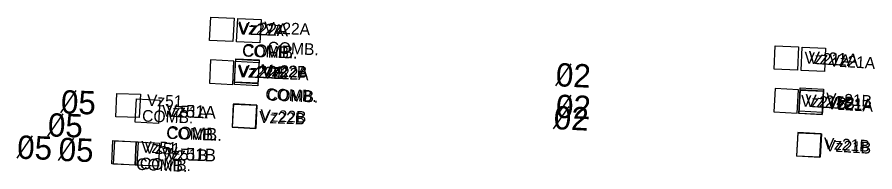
# Model space of a CAD drawing. Extents: x 647787 to 668496, y 640478 to 654412.
# Drawn here: x 660018.7 to 660238.8, y 647421.7 to 647461.5 of the extents above; entities that cross this region are included whole.
import ezdxf

# ---------------------------------------------------------------- set-up
doc = ezdxf.new("R2010")
doc.units = 0
for name, color, linetype in [('Default', 7, 'Continuous'), ('TEMP_DETECTION ZONE_Stage 2', 7, 'Continuous'), ('TEMP_DETECTION ZONE_STAGE 3', 7, 'Continuous'), ('TEMP_DETECTION_ZONE_STAGE 5', 7, 'Continuous'), ('TEMP_SIGNAL_POLES_STAGE 1B', 7, 'Continuous')]:
    doc.layers.add(name, color=color, linetype=linetype)

msp = doc.modelspace()

# ---------------------------------------------------------------- linework, layer by layer
at = {"layer": 'Default'}
for p, q in [((660156.89, 647443.78), (660160.86, 647449.48)), ((660156.89, 647443.78), (660160.86, 647449.48)), ((660156.89, 647443.78), (660160.86, 647449.48)), ((660029.94, 647436.81), (660033.86, 647442.55)), ((660156.89, 647435.68), (660160.86, 647441.38)), ((660156.36, 647432.75), (660160.33, 647438.45)), ((660026.6, 647430.88), (660030.52, 647436.62)), ((660026.6, 647430.88), (660030.52, 647436.62)), ((660018.73, 647425.14), (660022.65, 647430.89)), ((660029.35, 647424.57), (660033.27, 647430.32))]:
    msp.add_line(p, q, dxfattribs=at)
at = {"layer": 'TEMP_DETECTION ZONE_Stage 2'}
for p, q in [((660044.05, 647435.84), (660044.34, 647441.83)), ((660044.34, 647441.83), (660050.34, 647441.6)), ((660050.34, 647441.6), (660050.05, 647435.6)), ((660050.05, 647435.6), (660044.05, 647435.84))]:
    msp.add_line(p, q, dxfattribs=at)
for points in [[(660081.01, 647454.81), (660075.01, 647455.1), (660075.3, 647461.09), (660081.29, 647460.8)], [(660225.82, 647447.45), (660219.83, 647447.74), (660220.11, 647453.73), (660226.11, 647453.45)], [(660080.5, 647444.32), (660074.51, 647444.61), (660074.8, 647450.6), (660080.79, 647450.31)], [(660225.32, 647436.96), (660219.32, 647437.25), (660219.61, 647443.25), (660225.6, 647442.96)]]:
    msp.add_lwpolyline(points, close=True, dxfattribs=at)
at = {"layer": 'TEMP_DETECTION ZONE_STAGE 3'}
for p, q in [((660043.46, 647423.67), (660043.75, 647429.66)), ((660043.75, 647429.66), (660049.74, 647429.36)), ((660049.74, 647429.36), (660049.46, 647423.37)), ((660049.46, 647423.37), (660043.46, 647423.67))]:
    msp.add_line(p, q, dxfattribs=at)
for points in [[(660080.5, 647444.47), (660074.51, 647444.76), (660074.8, 647450.75), (660080.79, 647450.46)], [(660225.28, 647436.42), (660219.29, 647436.71), (660219.58, 647442.7), (660225.57, 647442.41)], [(660079.94, 647432.83), (660073.95, 647433.12), (660074.24, 647439.11), (660080.23, 647438.83)], [(660224.76, 647425.43), (660218.76, 647425.72), (660219.05, 647431.71), (660225.04, 647431.43)]]:
    msp.add_lwpolyline(points, close=True, dxfattribs=at)
at = {"layer": 'TEMP_DETECTION_ZONE_STAGE 5'}
for p, q in [((660068.08, 647455.46), (660068.39, 647461.46)), ((660068.39, 647461.46), (660074.38, 647461.15)), ((660074.38, 647461.15), (660074.07, 647455.16)), ((660074.07, 647455.16), (660068.08, 647455.46)), ((660212.9, 647448.11), (660213.2, 647454.1)), ((660213.2, 647454.1), (660219.19, 647453.79)), ((660219.19, 647453.79), (660218.89, 647447.81)), ((660068.34, 647450.44), (660068.04, 647444.45)), ((660074.33, 647450.14), (660068.34, 647450.44)), ((660074.03, 647444.15), (660074.33, 647450.14)), ((660074.45, 647444.13), (660074.76, 647450.12)), ((660074.76, 647450.12), (660080.75, 647449.81)), ((660080.75, 647449.81), (660080.45, 647443.82)), ((660218.89, 647447.81), (660212.9, 647448.11)), ((660068.04, 647444.45), (660074.03, 647444.15)), ((660080.45, 647443.82), (660074.45, 647444.13)), ((660213.15, 647443.09), (660212.85, 647437.1)), ((660219.15, 647442.77), (660213.15, 647443.09)), ((660218.84, 647436.78), (660219.15, 647442.77)), ((660219.57, 647442.75), (660219.26, 647436.76)), ((660225.56, 647442.42), (660219.57, 647442.75)), ((660225.25, 647436.42), (660225.56, 647442.42)), ((660049.02, 647434.4), (660049.32, 647440.4)), ((660055.31, 647440.09), (660055.01, 647434.1)), ((660074.19, 647439.13), (660073.89, 647433.14)), ((660080.18, 647438.83), (660074.19, 647439.13)), ((660079.88, 647432.84), (660080.18, 647438.83)), ((660212.85, 647437.1), (660218.84, 647436.78)), ((660219.26, 647436.76), (660225.25, 647436.42)), ((660073.89, 647433.14), (660079.88, 647432.84)), ((660042.98, 647423.7), (660043.28, 647429.69)), ((660043.28, 647429.69), (660049.27, 647429.38)), ((660219, 647431.76), (660218.7, 647425.77)), ((660225, 647431.43), (660219, 647431.76)), ((660224.69, 647425.44), (660225, 647431.43)), ((660049.27, 647429.38), (660048.97, 647423.39)), ((660048.97, 647423.39), (660049.27, 647429.38)), ((660049.27, 647429.38), (660055.27, 647429.08)), ((660055.27, 647429.08), (660054.96, 647423.09)), ((660218.7, 647425.77), (660224.69, 647425.44)), ((660048.97, 647423.39), (660042.98, 647423.7)), ((660054.96, 647423.09), (660048.97, 647423.39))]:
    msp.add_line(p, q, dxfattribs=at)
for points in [[(660049.32, 647440.4), (660055.31, 647440.09)], [(660055.01, 647434.1), (660049.02, 647434.4)]]:
    msp.add_lwpolyline(points, dxfattribs=at)
at = {"layer": 'TEMP_SIGNAL_POLES_STAGE 1B'}
for p, q in [((660068.08, 647455.46), (660068.39, 647461.46)), ((660068.39, 647461.46), (660074.38, 647461.15)), ((660074.38, 647461.15), (660074.07, 647455.16)), ((660074.07, 647455.16), (660068.08, 647455.46)), ((660212.9, 647448.11), (660213.2, 647454.1)), ((660213.2, 647454.1), (660219.19, 647453.79)), ((660219.19, 647453.79), (660218.89, 647447.81)), ((660068.34, 647450.44), (660068.04, 647444.45)), ((660074.33, 647450.14), (660068.34, 647450.44)), ((660074.03, 647444.15), (660074.33, 647450.14)), ((660218.89, 647447.81), (660212.9, 647448.11)), ((660068.04, 647444.45), (660074.03, 647444.15)), ((660213.15, 647443.09), (660212.85, 647437.1)), ((660219.15, 647442.77), (660213.15, 647443.09)), ((660218.84, 647436.78), (660219.15, 647442.77)), ((660049.02, 647434.4), (660049.32, 647440.4)), ((660055.31, 647440.09), (660055.01, 647434.1)), ((660212.85, 647437.1), (660218.84, 647436.78)), ((660048.97, 647423.39), (660049.27, 647429.38)), ((660049.27, 647429.38), (660055.27, 647429.08)), ((660055.27, 647429.08), (660054.96, 647423.09)), ((660054.96, 647423.09), (660048.97, 647423.39))]:
    msp.add_line(p, q, dxfattribs=at)
for points in [[(660049.32, 647440.4), (660055.31, 647440.09)], [(660055.01, 647434.1), (660049.02, 647434.4)]]:
    msp.add_lwpolyline(points, dxfattribs=at)

# ---------------------------------------------------------------- texts
at = {"layer": 'Default'}
for s, rotation, p in [('02', 357.3266, (660156.83, 647443.69)), ('02', 357.3266, (660156.83, 647443.69)), ('02', 357.3266, (660156.83, 647443.69)), ('05', 357.8528, (660029.88, 647436.72)), ('02', 357.3266, (660156.83, 647435.59)), ('02', 357.3266, (660156.29, 647432.66)), ('05', 357.8528, (660026.54, 647430.79)), ('05', 357.8528, (660026.54, 647430.79)), ('05', 357.8528, (660018.66, 647425.06)), ('05', 357.8528, (660029.29, 647424.49))]:
    msp.add_text(s, height=6, rotation=rotation, dxfattribs=at).set_placement(p)
at = {"layer": 'TEMP_DETECTION ZONE_Stage 2'}
for s, rotation, p in [('Vz22A', 357.6447, (660082.01, 647457.29)), ('COMB.', 357.6447, (660082.91, 647452.17)), ('Vz21A', 356.5579, (660226.97, 647448.83)), ('Vz22B', 357.6447, (660081.28, 647446.28)), ('Vz51', 357.7614, (660051.95, 647438.63)), ('Vz21B', 356.5579, (660226.12, 647439.05)), ('COMB.', 357.7614, (660050.74, 647434.61))]:
    msp.add_text(s, height=3, rotation=rotation, dxfattribs=at).set_placement(p)
at = {"layer": 'TEMP_DETECTION ZONE_STAGE 3'}
for s, rotation, p in [('Vz22A', 357.6447, (660081.47, 647446.31)), ('COMB.', 357.6447, (660082.38, 647440.18)), ('Vz21A', 356.5579, (660226.43, 647437.8)), ('Vz22B', 357.6447, (660080.75, 647434.29)), ('Vz21B', 356.5579, (660225.56, 647427.52)), ('Vz51', 357.7614, (660051.36, 647426.39)), ('COMB.', 357.7614, (660050.15, 647422.37))]:
    msp.add_text(s, height=3, rotation=rotation, dxfattribs=at).set_placement(p)
at = {"layer": 'TEMP_DETECTION_ZONE_STAGE 5'}
for s, rotation, p in [('Vz22A', 357.6447, (660075.27, 647457.04)), ('COMB.', 357.6447, (660076.41, 647451.35)), ('Vz21A', 356.5579, (660220.57, 647449.55)), ('Vz22B', 357.6447, (660075.21, 647446.03)), ('Vz22A', 357.6447, (660081.64, 647445.71)), ('COMB.', 357.6447, (660082.78, 647440.01)), ('Vz21B', 356.5579, (660219.67, 647438.48)), ('Vz21A', 356.5579, (660226.35, 647438.09)), ('Vz51A', 357.6447, (660055.8, 647435.9)), ('Vz22B', 357.6447, (660081.06, 647434.72)), ('COMB.', 357.6447, (660056.94, 647430.2)), ('Vz51', 357.6447, (660050.45, 647426.64)), ('Vz21B', 356.5579, (660225.94, 647427)), ('Vz51B', 357.6447, (660055.75, 647424.88)), ('COMB.', 357.6447, (660049.22, 647422.18))]:
    msp.add_text(s, height=3, rotation=rotation, dxfattribs=at).set_placement(p)
at = {"layer": 'TEMP_SIGNAL_POLES_STAGE 1B'}
for s, rotation, p in [('Vz22A', 357.6447, (660075.41, 647457.04)), ('COMB.', 357.6447, (660076.43, 647451.35)), ('Vz21A', 356.5579, (660221.63, 647449.49)), ('Vz22B', 357.6447, (660075.41, 647446.02)), ('Vz21B', 356.5579, (660220.8, 647438.41)), ('Vz51A', 357.6447, (660056.86, 647435.85)), ('COMB.', 357.6447, (660056.97, 647430.2)), ('Vz51B', 357.6447, (660056.87, 647424.83))]:
    msp.add_text(s, height=3.25, rotation=rotation, dxfattribs=at).set_placement(p)

doc.saveas('drawing.dxf')
